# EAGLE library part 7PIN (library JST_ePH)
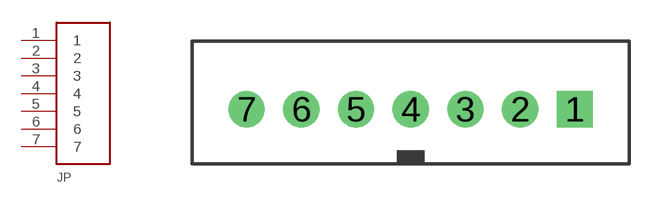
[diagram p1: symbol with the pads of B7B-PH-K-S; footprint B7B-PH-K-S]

Designator prefix JP

## 7PIN  [B7B-PH-K-S]
1  1
2  2
3  3
4  4
5  5
6  6
7  7

## Footprint B7B-PH-K-S (pad centres in mm)
drill 0.813 square: 1 6,0
drill 0.813 round: 2 4,0; 3 2,0; 4 0,0; 5 -2,0; 6 -4,0; 7 -6,0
